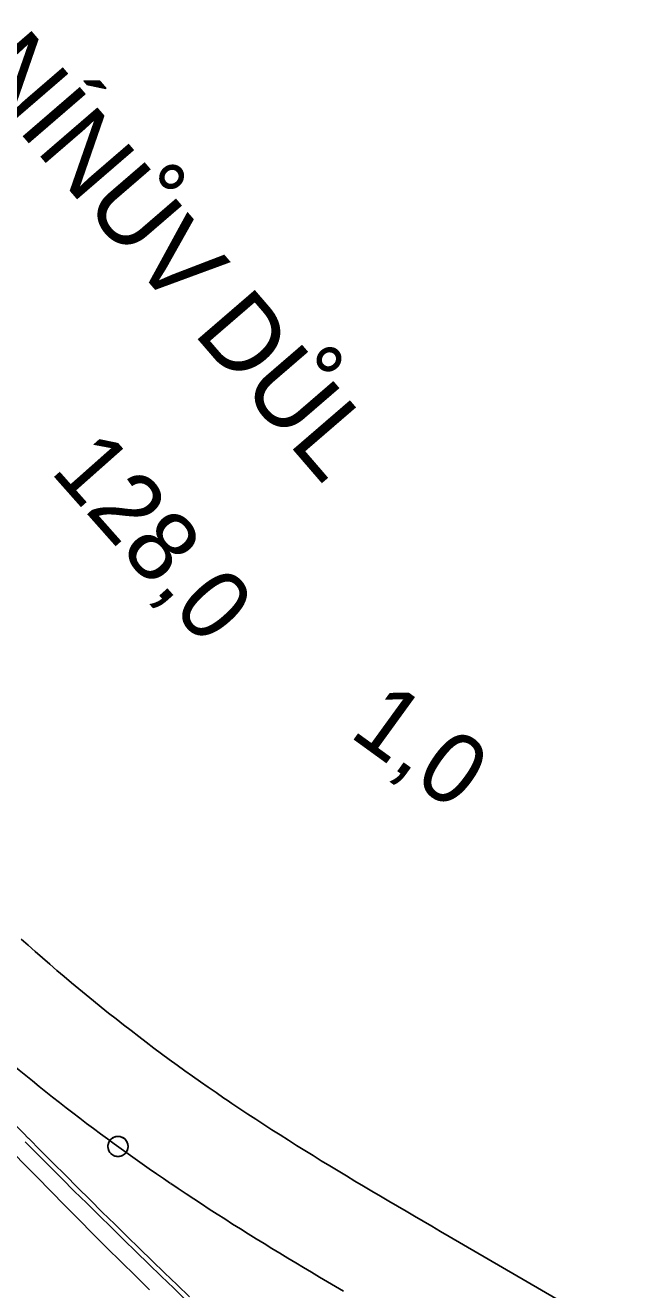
# Model space of a CAD drawing. Extents: x -670810 to -649614, y -1131928 to -1115069.
# Drawn here: x -668186 to -667569, y -1123186 to -1121929 of the extents above; entities that cross this region are included whole.
import ezdxf

# ---------------------------------------------------------------- set-up
doc = ezdxf.new("R2010")
doc.units = 0
for name, color, linetype in [('519 Var SK-4 Praporky stanic', 7, 'Continuous'), ('hranice_VRT_ZUR_Vysocina', 7, 'Continuous'), ('Situace - Osa koleje 2D', 7, 'Continuous'), ('Staničení - hlavní staničení + kolečka 1k', 7, 'Continuous')]:
    doc.layers.add(name, color=color, linetype=linetype)

# ---------------------------------------------------------------- blocks, each defined once
blk = doc.blocks.new('Sit10Kruh_168')
at = {"layer": 'Staničení - hlavní staničení + kolečka 1k'}
blk.add_lwpolyline([(10, 0), (10, 0.6), (9.9, 1.3), (9.8, 1.9), (9.7, 2.5), (9.5, 3.1), (9.3, 3.7), (9, 4.3), (8.8, 4.8), (8.4, 5.4), (8.1, 5.9), (7.7, 6.4), (7.3, 6.8), (6.8, 7.3), (6.4, 7.7), (5.9, 8.1), (5.4, 8.4), (4.8, 8.8), (4.3, 9), (3.7, 9.3), (3.1, 9.5), (2.5, 9.7), (1.9, 9.8), (1.3, 9.9), (0.6, 10), (0, 10), (-0.6, 10), (-1.3, 9.9), (-1.9, 9.8), (-2.5, 9.7), (-3.1, 9.5), (-3.7, 9.3), (-4.3, 9), (-4.8, 8.8), (-5.4, 8.4), (-5.9, 8.1), (-6.4, 7.7), (-6.8, 7.3), (-7.3, 6.8), (-7.7, 6.4), (-8.1, 5.9), (-8.4, 5.4), (-8.8, 4.8), (-9, 4.3), (-9.3, 3.7), (-9.5, 3.1), (-9.7, 2.5), (-9.8, 1.9), (-9.9, 1.3), (-10, 0.6), (-10, 0), (-10, -0.6), (-9.9, -1.3), (-9.8, -1.9), (-9.7, -2.5), (-9.5, -3.1), (-9.3, -3.7), (-9, -4.3), (-8.8, -4.8), (-8.4, -5.4), (-8.1, -5.9), (-7.7, -6.4), (-7.3, -6.8), (-6.8, -7.3), (-6.4, -7.7), (-5.9, -8.1), (-5.4, -8.4), (-4.8, -8.8), (-4.3, -9), (-3.7, -9.3), (-3.1, -9.5), (-2.5, -9.7), (-1.9, -9.8), (-1.3, -9.9), (-0.6, -10), (0, -10), (0.6, -10), (1.3, -9.9), (1.9, -9.8), (2.5, -9.7), (3.1, -9.5), (3.7, -9.3), (4.3, -9), (4.8, -8.8), (5.4, -8.4), (5.9, -8.1), (6.4, -7.7), (6.8, -7.3), (7.3, -6.8), (7.7, -6.4), (8.1, -5.9), (8.4, -5.4), (8.8, -4.8), (9, -4.3), (9.3, -3.7), (9.5, -3.1), (9.7, -2.5), (9.8, -1.9), (9.9, -1.3)], close=True, dxfattribs=at)
blk.add_circle((0, 0), 10, dxfattribs=at)
blk = doc.blocks.new('_U496')
at = {"layer": '519 Var SK-4 Praporky stanic'}
blk.add_text('ODB ANTONÍNŮV DŮL', height=75, dxfattribs=at).set_placement((-432.7, 274.9))

msp = doc.modelspace()

# ---------------------------------------------------------------- linework, layer by layer
at = {"layer": 'hranice_VRT_ZUR_Vysocina'}
msp.add_lwpolyline([(-668190, -1122837.4), (-668183, -1122843.6), (-668175.9, -1122849.9), (-668168.7, -1122856.2), (-668161.6, -1122862.4), (-668154.4, -1122868.6), (-668147.1, -1122874.8), (-668139.9, -1122880.9), (-668132.6, -1122887), (-668125.2, -1122893), (-668117.9, -1122899), (-668110.5, -1122905), (-668103.1, -1122911), (-668095.6, -1122916.9), (-668088.2, -1122922.7), (-668080.7, -1122928.5), (-668073.1, -1122934.3), (-668065.6, -1122940.1), (-668058, -1122945.8), (-668050.3, -1122951.5), (-668042.7, -1122957.1), (-668035, -1122962.7), (-668027.3, -1122968.3), (-668019.6, -1122973.8), (-668011.8, -1122979.3), (-668004, -1122984.7), (-667996.2, -1122990.1), (-667988.3, -1122995.5), (-667985.2, -1122997.6), (-667980.6, -1123000.8), (-667972.6, -1123006.1), (-667964.7, -1123011.4), (-667956.7, -1123016.6), (-667948.6, -1123021.8), (-667940.6, -1123027), (-667932.5, -1123032.2), (-667924.3, -1123037.4), (-667916.2, -1123042.5), (-667908, -1123047.6), (-667899.7, -1123052.7), (-667891.5, -1123057.8), (-667883.2, -1123062.8), (-667874.9, -1123067.9), (-667866.5, -1123072.9), (-667858.1, -1123078), (-667849.7, -1123083), (-667841.3, -1123088), (-667832.8, -1123093), (-667824.4, -1123098), (-667815.9, -1123103), (-667807.3, -1123108), (-667798.8, -1123113), (-667790.2, -1123118), (-667781.6, -1123123), (-667773, -1123128), (-667764.4, -1123133), (-666960.3, -1123600.4)], dxfattribs=at)
at = {"layer": 'Situace - Osa koleje 2D'}
for points in [[(-668185.9, -1123038.9), (-668173.7, -1123051.2), (-668161.5, -1123063.4), (-668149.3, -1123075.7), (-668137.1, -1123087.9), (-668124.8, -1123100), (-668112.5, -1123112.2), (-668100.2, -1123124.3), (-668087.9, -1123136.4), (-668075.5, -1123148.5), (-668063.1, -1123160.5), (-668050.7, -1123172.6), (-668038.3, -1123184.6), (-668025.8, -1123196.6)], [(-668182.6, -1123035.5), (-668170.4, -1123047.8), (-668158.2, -1123060.1), (-668146, -1123072.3), (-668133.8, -1123084.5), (-668121.5, -1123096.7), (-668109.3, -1123108.8), (-668096.9, -1123120.9), (-668084.6, -1123133), (-668072.2, -1123145.1), (-668059.8, -1123157.2), (-668047.4, -1123169.2), (-668035, -1123181.2), (-668022.6, -1123193.2)], [(-668041.3, -1123080.4), (-668033.7, -1123085.5), (-668026, -1123090.7), (-668018.4, -1123095.7), (-668010.7, -1123100.8), (-668003, -1123105.8), (-667995.2, -1123110.8), (-667987.5, -1123115.7), (-667979.7, -1123120.7), (-667971.9, -1123125.6), (-667964.1, -1123130.4), (-667956.3, -1123135.3), (-667948.5, -1123140.1), (-667940.6, -1123144.9), (-667932.8, -1123149.7), (-667924.9, -1123154.5), (-667917, -1123159.2), (-667909.1, -1123164), (-667901.2, -1123168.7), (-667893.3, -1123173.4), (-667885.4, -1123178.1), (-667877.5, -1123182.8), (-667869.6, -1123187.4)]]:
    msp.add_lwpolyline(points, dxfattribs=at)
for centre, radius, start, end in [((-663806.8, -1118815.5), 6100, 219.80976, 225.76422), ((-663197.7, -1118121.2), 7000, 222.54508, 224.5916), ((-666919.5, -1121424.7), 2000, 228.0357, 235.88)]:
    msp.add_arc(centre, radius, start, end, dxfattribs=at)

# ---------------------------------------------------------------- block references
at = {"layer": '519 Var SK-4 Praporky stanic', "rotation": -49.222906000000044}
msp.add_blockref('_U496', (-668509.5, -1122088.1), dxfattribs=at)
at = {"layer": 'Staničení - hlavní staničení + kolečka 1k', "rotation": -35.95414599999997}
msp.add_blockref('Sit10Kruh_168', (-668093.7, -1123043.6), dxfattribs=at)

# ---------------------------------------------------------------- texts
at = {"layer": 'Staničení - hlavní staničení + kolečka 1k'}
for s, rotation, p in [('128,0', 311.548, (-668162, -1122372.6)), ('1,0', 324.0458, (-667865.2, -1122634.9))]:
    msp.add_text(s, height=70, rotation=rotation, dxfattribs=at).set_placement(p)

doc.saveas('drawing.dxf')
